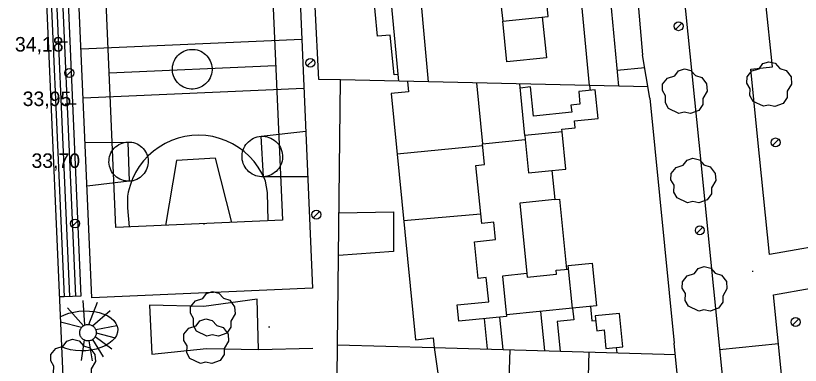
# Model space of a CAD drawing. Extents: x 431390 to 432653, y 4586754 to 4589600.
# Drawn here: x 431800 to 431870.2, y 4586907.1 to 4586938.4 of the extents above; entities that cross this region are included whole.
import ezdxf

# ---------------------------------------------------------------- set-up
doc = ezdxf.new("R2010")
doc.units = 0
for name, color, linetype in [('COM_17LS_LN', 7, 'Continuous'), ('COM_51_LN', 7, 'Continuous'), ('CON_01_LN', 7, 'Continuous'), ('CON_01FI_LN', 7, 'Continuous'), ('CON_03_LN', 7, 'Continuous'), ('CON_04_LN', 7, 'Continuous'), ('CON_15_LN', 7, 'Continuous'), ('CON_16_LN', 7, 'Continuous'), ('CON_18LS_LN', 7, 'Continuous'), ('CON_19_LN', 7, 'Continuous'), ('CON_23_LN', 7, 'Continuous'), ('CON_24LS_LN', 7, 'Continuous'), ('ENE_06_PT', 7, 'Continuous'), ('ORO_03_PT', 7, 'Continuous'), ('ORO_04_PT', 7, 'Continuous'), ('ORO_04_TX', 7, 'Continuous'), ('VEG_03_PT', 7, 'Continuous')]:
    doc.layers.add(name, color=color, linetype=linetype)

msp = doc.modelspace()

# ---------------------------------------------------------------- linework, layer by layer
at = {"layer": 'COM_17LS_LN'}
for points in [[(431853.209, 4587026.07), (431851.172, 4587025.865), (431854.479, 4586993.032), (431857.953, 4586958.536), (431861.124, 4586927.05), (431865.053, 4586888.028), (431868.58, 4586853.01), (431870.706, 4586853.224), (431871.5, 4586845.327)], [(431978.482, 4586940.712), (431979.21, 4586936.465), (431977.301, 4586936.133), (431968.138, 4586934.539), (431952.481, 4586931.815), (431928.554, 4586927.652), (431912.203, 4586924.807), (431895.247, 4586921.857), (431873.934, 4586918.149), (431867.46, 4586917.026), (431866.397, 4586927.581), (431865.787, 4586933.635), (431867.716, 4586933.829), (431867.112, 4586939.828), (431865.183, 4586939.634), (431863.226, 4586959.067), (431861.278, 4586978.415)], [(431874.91, 4586845.69), (431873.853, 4586853.541), (431873.729, 4586854.767), (431875.087, 4586854.904), (431874.927, 4586856.495), (431873.569, 4586856.358), (431870.326, 4586888.559), (431867.823, 4586913.416), (431874.552, 4586914.603), (431895.864, 4586918.311), (431912.821, 4586921.261), (431929.172, 4586924.106), (431935.982, 4586925.291)]]:
    msp.add_lwpolyline(points, dxfattribs=at)
at = {"layer": 'COM_51_LN'}
msp.add_lwpolyline([(431868.266, 4586909.012), (431862.994, 4586908.481)], dxfattribs=at)
at = {"layer": 'CON_01_LN'}
for points in [[(431854.203, 4586956.737), (431856.092, 4586934.904)], [(431856.756, 4586931.032), (431856.092, 4586934.904)], [(431856.756, 4586931.032), (431858.937, 4586909.088)], [(431859.921, 4586899.186), (431858.937, 4586909.088)]]:
    msp.add_lwpolyline(points, dxfattribs=at)
at = {"layer": 'CON_01FI_LN'}
for points in [[(431828.804, 4586908.95), (431829.048, 4586932.666), (431827.13, 4586932.71), (431825.8, 4586958.75)], [(431801.98, 4586957.34), (431806.03, 4586864.43), (431833.508, 4586863.83), (431833.576, 4586865.966), (431837.653, 4586865.916), (431837.679, 4586868.022), (431838.021, 4586873.777), (431833.823, 4586873.778), (431833.91, 4586876.529), (431842.85, 4586876.74), (431852.851, 4586877.287), (431852.6, 4586881.16), (431848.78, 4586880.94), (431848.8, 4586882.78), (431845.66, 4586882.65), (431845.641, 4586885.215), (431839.319, 4586885.285), (431828.566, 4586885.721)], [(431828.804, 4586908.95), (431837.436, 4586908.702), (431838.09, 4586904.139), (431841.489, 4586904.07), (431841.411, 4586899.722), (431828.713, 4586900.09), (431828.566, 4586885.721)]]:
    msp.add_lwpolyline(points, dxfattribs=at)
at = {"layer": 'CON_03_LN'}
for points in [[(431856.585, 4586932.03), (431829.048, 4586932.666)], [(431837.436, 4586908.702), (431859.037, 4586908.081)]]:
    msp.add_lwpolyline(points, dxfattribs=at)
at = {"layer": 'CON_04_LN'}
for points in [[(431853.962, 4586932.091), (431851.55, 4586957.907)], [(431832.476, 4586957.35), (431832.11, 4586955.39), (431834.252, 4586932.546)], [(431848.912, 4586957.642), (431851.315, 4586932.152)], [(431835.115, 4586956.796), (431834.86, 4586955.22), (431836.918, 4586932.484)], [(431834.195, 4586933.154), (431833.853, 4586933.122), (431833.519, 4586936.676), (431832.357, 4586936.567), (431831.729, 4586943.247), (431832.87, 4586943.354), (431832.462, 4586947.694), (431831.302, 4586947.585), (431830.956, 4586951.263), (431832.219, 4586951.382), (431832.06, 4586953.075), (431832.325, 4586953.1)], [(431847.196, 4586942.871), (431840.47, 4586942.18), (431840.78, 4586939.161), (431843.421, 4586939.432), (431843.575, 4586937.932), (431847.66, 4586938.351), (431847.196, 4586942.871)], [(431847.124, 4586938.296), (431847.499, 4586934.639), (431843.95, 4586934.275), (431843.575, 4586937.932)], [(431856.294, 4586933.729), (431853.83, 4586933.502)], [(431835.048, 4586932.527), (431835.14, 4586931.6), (431833.579, 4586931.445), (431835.769, 4586909.397), (431837.351, 4586909.554), (431837.436, 4586908.702)], [(431841.806, 4586926.95), (431841.267, 4586932.384)], [(431845.567, 4586927.674), (431845.105, 4586932.295)], [(431848.889, 4586928.006), (431848.865, 4586928.244), (431850.071, 4586928.365), (431850.007, 4586929.008), (431852.117, 4586929.219), (431851.862, 4586931.762), (431850.378, 4586931.613), (431850.491, 4586930.488), (431849.688, 4586930.408), (431849.752, 4586929.77), (431846.324, 4586929.427), (431846.064, 4586932.026), (431845.141, 4586931.933)], [(431851.433, 4586931.719), (431851.389, 4586932.15)], [(431847.973, 4586924.556), (431849.221, 4586924.681), (431848.889, 4586928.006), (431845.567, 4586927.674), (431845.602, 4586927.327)], [(431843.92, 4586911.47), (431839.641, 4586911.045), (431839.496, 4586912.506), (431842.326, 4586912.787), (431842.111, 4586914.955), (431841.391, 4586914.883), (431841.064, 4586918.17), (431842.926, 4586918.355), (431842.772, 4586919.907), (431841.698, 4586919.8), (431841.182, 4586924.996), (431841.94, 4586925.071), (431841.754, 4586926.945), (431845.602, 4586927.327), (431845.898, 4586924.35), (431847.973, 4586924.556), (431848.233, 4586921.943), (431845.103, 4586921.632), (431845.731, 4586915.312), (431843.56, 4586915.096), (431843.92, 4586911.47)], [(431841.772, 4586926.763), (431834.119, 4586926.005)], [(431848.233, 4586921.943), (431848.673, 4586921.987), (431849.297, 4586915.701)], [(431828.926, 4586920.77), (431833.8, 4586920.86), (431833.8, 4586917.28), (431828.886, 4586916.951)], [(431841.615, 4586920.634), (431834.71, 4586920.055)], [(431849.45, 4586916.042), (431851.597, 4586916.255), (431851.978, 4586912.423), (431849.831, 4586912.21), (431849.45, 4586916.042)], [(431845.731, 4586915.312), (431845.762, 4586914.999), (431848.398, 4586915.264), (431848.363, 4586915.608), (431849.482, 4586915.72)], [(431849.831, 4586912.21), (431843.905, 4586911.619)], [(431849.831, 4586912.21), (431849.929, 4586911.172), (431848.462, 4586911.025), (431848.726, 4586908.377)], [(431851.439, 4586912.37), (431851.565, 4586911.096), (431851.906, 4586911.13)], [(431843.294, 4586911.408), (431843.58, 4586908.525)], [(431846.972, 4586911.925), (431847.322, 4586908.418)], [(431854.026, 4586911.744), (431851.866, 4586911.527), (431851.999, 4586910.2), (431852.647, 4586910.265), (431852.814, 4586908.604), (431854.326, 4586908.756), (431854.026, 4586911.744)], [(431841.93, 4586911.272), (431842.199, 4586908.565)], [(431853.747, 4586908.698), (431853.794, 4586908.232)], [(431844.202, 4586908.507), (431844.073, 4586904.017)], [(431851.281, 4586908.304), (431851.154, 4586903.873)]]:
    msp.add_lwpolyline(points, dxfattribs=at)
at = {"layer": 'CON_15_LN'}
msp.add_lwpolyline([(431821.72, 4586908.53), (431821.61, 4586913.03), (431816.82, 4586912.36), (431811.95, 4586912.49), (431812.18, 4586908.1), (431817.07, 4586908.61), (431821.72, 4586908.53)], dxfattribs=at)
at = {"layer": 'CON_16_LN'}
msp.add_lwpolyline([(431828.713, 4586900.09), (431828.804, 4586908.95)], dxfattribs=at)
at = {"layer": 'CON_18LS_LN'}
for points in [[(431802.213, 4586952.001), (431802.637, 4586952.019), (431804.137, 4586952.084), (431805.827, 4586913.305), (431804.327, 4586913.24), (431803.903, 4586913.221)], [(431802.637, 4586952.019), (431804.327, 4586913.24)], [(431804.827, 4586913.262), (431803.137, 4586952.041)], [(431803.637, 4586952.062), (431805.327, 4586913.283)]]:
    msp.add_lwpolyline(points, dxfattribs=at)
at = {"layer": 'CON_19_LN'}
msp.add_lwpolyline([(431821.72, 4586908.53), (431826.59, 4586908.65)], dxfattribs=at)
at = {"layer": 'CON_23_LN'}
for points in [[(431806.177, 4586910.713), (431806.016, 4586912.893)], [(431806.534, 4586910.763), (431807.298, 4586912.77)], [(431806.048, 4586910.645), (431804.632, 4586912.264)], [(431803.981, 4586911.436), (431804.348, 4586911.617), (431804.755, 4586911.764), (431805.192, 4586911.875), (431805.65, 4586911.946), (431806.117, 4586911.977), (431806.583, 4586911.966), (431807.037, 4586911.913), (431807.468, 4586911.821), (431807.866, 4586911.69), (431808.222, 4586911.524), (431808.529, 4586911.328), (431808.777, 4586911.104), (431808.963, 4586910.86), (431809.08, 4586910.6), (431809.128, 4586910.33), (431809.104, 4586910.057), (431809.009, 4586909.787), (431808.846, 4586909.526), (431808.618, 4586909.281), (431808.33, 4586909.057), (431807.99, 4586908.859), (431807.604, 4586908.693), (431807.183, 4586908.561), (431806.735, 4586908.467), (431806.272, 4586908.413), (431805.804, 4586908.401), (431805.342, 4586908.43), (431804.897, 4586908.5), (431804.479, 4586908.61), (431804.098, 4586908.756)], [(431806.874, 4586910.64), (431808.446, 4586912.004)], [(431805.885, 4586910.499), (431804.002, 4586910.957)], [(431807.11, 4586909.67), (431807.072, 4586909.608), (431807.028, 4586909.549), (431806.979, 4586909.496), (431806.925, 4586909.447), (431806.866, 4586909.404), (431806.803, 4586909.367), (431806.737, 4586909.336), (431806.668, 4586909.312), (431806.597, 4586909.295), (431806.525, 4586909.284), (431806.452, 4586909.281), (431806.379, 4586909.285), (431806.307, 4586909.297), (431806.237, 4586909.315), (431806.168, 4586909.34), (431806.102, 4586909.371), (431806.04, 4586909.409), (431805.982, 4586909.453), (431805.928, 4586909.502), (431805.879, 4586909.557), (431805.836, 4586909.615), (431805.799, 4586909.678), (431805.769, 4586909.744), (431805.744, 4586909.813), (431805.727, 4586909.884), (431805.717, 4586909.956), (431805.714, 4586910.029), (431805.718, 4586910.102), (431805.729, 4586910.174), (431805.747, 4586910.245), (431805.772, 4586910.313), (431805.804, 4586910.379), (431805.842, 4586910.441), (431805.885, 4586910.499), (431805.935, 4586910.553), (431805.989, 4586910.602), (431806.048, 4586910.645), (431806.111, 4586910.682), (431806.177, 4586910.713), (431806.246, 4586910.737), (431806.317, 4586910.754), (431806.389, 4586910.764), (431806.462, 4586910.768), (431806.534, 4586910.763), (431806.606, 4586910.752), (431806.677, 4586910.734), (431806.746, 4586910.709), (431806.811, 4586910.678), (431806.874, 4586910.64), (431806.932, 4586910.596), (431806.986, 4586910.547), (431807.034, 4586910.492), (431807.077, 4586910.433), (431807.114, 4586910.371), (431807.145, 4586910.304), (431807.169, 4586910.236), (431807.187, 4586910.165), (431807.197, 4586910.093), (431807.2, 4586910.02), (431807.196, 4586909.947), (431807.185, 4586909.875), (431807.167, 4586909.804), (431807.142, 4586909.736), (431807.11, 4586909.67)], [(431807.145, 4586910.304), (431809.045, 4586910.677)], [(431807.2, 4586910.02), (431808.877, 4586909.575)], [(431806.102, 4586909.371), (431805.858, 4586907.534)], [(431806.525, 4586909.284), (431806.828, 4586907.509)], [(431806.866, 4586909.404), (431807.818, 4586907.87)], [(431807.11, 4586909.67), (431808.596, 4586908.579)]]:
    msp.add_lwpolyline(points, dxfattribs=at)
at = {"layer": 'CON_24LS_LN'}
for points in [[(431805.108, 4586952.126), (431824.867, 4586952.987), (431826.566, 4586914.02), (431806.807, 4586913.159), (431805.108, 4586952.126)], [(431807.75, 4586947.261), (431822.646, 4586947.91), (431823.859, 4586920.092), (431808.963, 4586919.443), (431807.75, 4586947.261)], [(431825.596, 4586936.273), (431805.837, 4586935.411)], [(431814.013, 4586933.542), (431814.014, 4586933.716), (431814.032, 4586933.89), (431814.067, 4586934.06), (431814.118, 4586934.227), (431814.186, 4586934.387), (431814.269, 4586934.541), (431814.367, 4586934.685), (431814.478, 4586934.819), (431814.602, 4586934.942), (431814.737, 4586935.051), (431814.882, 4586935.147), (431815.037, 4586935.229), (431815.198, 4586935.295), (431815.365, 4586935.344), (431815.536, 4586935.377), (431815.709, 4586935.393), (431815.884, 4586935.393), (431816.057, 4586935.375), (431816.228, 4586935.34), (431816.394, 4586935.288), (431816.555, 4586935.221), (431816.708, 4586935.138), (431816.853, 4586935.04), (431816.987, 4586934.929), (431817.109, 4586934.805), (431817.219, 4586934.67), (431817.315, 4586934.524), (431817.396, 4586934.37), (431817.462, 4586934.209), (431817.512, 4586934.042), (431817.545, 4586933.871), (431817.561, 4586933.697), (431817.56, 4586933.523), (431817.542, 4586933.349), (431817.507, 4586933.179), (431817.456, 4586933.012), (431817.388, 4586932.852), (431817.305, 4586932.698), (431817.207, 4586932.554), (431817.096, 4586932.42), (431816.972, 4586932.297), (431816.837, 4586932.188), (431816.692, 4586932.092), (431816.537, 4586932.01), (431816.376, 4586931.944), (431816.209, 4586931.895), (431816.038, 4586931.862), (431815.865, 4586931.846), (431815.69, 4586931.846), (431815.517, 4586931.864), (431815.346, 4586931.899), (431815.18, 4586931.951), (431815.019, 4586932.018), (431814.866, 4586932.101), (431814.721, 4586932.199), (431814.587, 4586932.31), (431814.465, 4586932.434), (431814.355, 4586932.569), (431814.259, 4586932.715), (431814.178, 4586932.869), (431814.112, 4586933.03), (431814.062, 4586933.197), (431814.029, 4586933.368), (431814.013, 4586933.542)], [(431808.359, 4586933.295), (431823.255, 4586933.945)], [(431806.027, 4586931.049), (431825.786, 4586931.91)], [(431822.582, 4586920.036), (431822.515, 4586922.591), (431822.341, 4586923.59), (431822.289, 4586923.737), (431822.021, 4586924.305), (431821.699, 4586924.844), (431821.325, 4586925.349), (431820.905, 4586925.816), (431820.44, 4586926.239), (431819.937, 4586926.614), (431819.399, 4586926.939), (431818.833, 4586927.209), (431818.242, 4586927.423), (431817.634, 4586927.579), (431817.013, 4586927.674), (431816.386, 4586927.708), (431815.758, 4586927.681), (431815.136, 4586927.592), (431814.526, 4586927.443), (431813.933, 4586927.236), (431813.364, 4586926.971), (431812.823, 4586926.652), (431812.315, 4586926.282), (431811.847, 4586925.864), (431811.421, 4586925.403), (431811.042, 4586924.902), (431810.714, 4586924.366), (431810.44, 4586923.801), (431810.223, 4586923.212), (431810.064, 4586922.604), (431810.007, 4586922.245), (431809.986, 4586921.21), (431810.147, 4586919.495)], [(431821.95, 4586927.61), (431822.128, 4586927.612), (431822.306, 4586927.597), (431822.481, 4586927.564), (431822.652, 4586927.514), (431822.817, 4586927.448), (431822.975, 4586927.366), (431823.124, 4586927.269), (431823.263, 4586927.158), (431823.391, 4586927.033), (431823.505, 4586926.897), (431823.606, 4586926.75), (431823.692, 4586926.594), (431823.762, 4586926.43), (431823.816, 4586926.26), (431823.852, 4586926.086), (431823.872, 4586925.909), (431823.874, 4586925.731), (431823.859, 4586925.553), (431823.826, 4586925.378), (431823.776, 4586925.207), (431823.71, 4586925.042), (431823.628, 4586924.884), (431823.531, 4586924.735), (431823.42, 4586924.596), (431823.295, 4586924.468), (431823.159, 4586924.354), (431823.012, 4586924.253), (431822.856, 4586924.167), (431822.692, 4586924.097), (431822.522, 4586924.043), (431822.348, 4586924.007), (431822.171, 4586923.987), (431821.993, 4586923.985), (431821.815, 4586924), (431821.64, 4586924.033), (431821.469, 4586924.083), (431821.304, 4586924.149), (431821.146, 4586924.231), (431820.997, 4586924.328), (431820.858, 4586924.439), (431820.73, 4586924.564), (431820.616, 4586924.7), (431820.515, 4586924.847), (431820.429, 4586925.003), (431820.359, 4586925.167), (431820.305, 4586925.337), (431820.269, 4586925.511), (431820.249, 4586925.688), (431820.247, 4586925.866), (431820.262, 4586926.044), (431820.295, 4586926.219), (431820.345, 4586926.39), (431820.411, 4586926.555), (431820.493, 4586926.713), (431820.59, 4586926.862), (431820.701, 4586927.001), (431820.826, 4586927.129), (431820.962, 4586927.243), (431821.109, 4586927.344), (431821.265, 4586927.43), (431821.429, 4586927.5), (431821.599, 4586927.554), (431821.773, 4586927.59), (431821.95, 4586927.61)], [(431826.131, 4586923.989), (431822.171, 4586923.987), (431821.95, 4586927.61), (431825.953, 4586928.07)], [(431806.201, 4586927.047), (431810.03, 4586927.1), (431810.15, 4586923.59), (431806.372, 4586923.145)], [(431810.03, 4586927.1), (431810.202, 4586927.097), (431810.374, 4586927.078), (431810.542, 4586927.042), (431810.706, 4586926.989), (431810.864, 4586926.921), (431811.015, 4586926.838), (431811.157, 4586926.74), (431811.289, 4586926.628), (431811.409, 4586926.505), (431811.516, 4586926.37), (431811.609, 4586926.225), (431811.688, 4586926.072), (431811.752, 4586925.912), (431811.8, 4586925.746), (431811.831, 4586925.577), (431811.845, 4586925.405), (431811.842, 4586925.233), (431811.823, 4586925.061), (431811.787, 4586924.893), (431811.734, 4586924.729), (431811.666, 4586924.571), (431811.583, 4586924.42), (431811.485, 4586924.278), (431811.373, 4586924.146), (431811.25, 4586924.026), (431811.115, 4586923.919), (431810.97, 4586923.826), (431810.817, 4586923.747), (431810.657, 4586923.683), (431810.491, 4586923.635), (431810.322, 4586923.604), (431810.15, 4586923.59), (431809.978, 4586923.593), (431809.806, 4586923.612), (431809.638, 4586923.648), (431809.474, 4586923.701), (431809.316, 4586923.769), (431809.165, 4586923.852), (431809.023, 4586923.95), (431808.891, 4586924.062), (431808.771, 4586924.185), (431808.664, 4586924.32), (431808.571, 4586924.465), (431808.492, 4586924.618), (431808.428, 4586924.778), (431808.38, 4586924.944), (431808.349, 4586925.113), (431808.335, 4586925.285), (431808.338, 4586925.457), (431808.357, 4586925.629), (431808.393, 4586925.797), (431808.446, 4586925.961), (431808.514, 4586926.119), (431808.597, 4586926.27), (431808.695, 4586926.412), (431808.807, 4586926.544), (431808.93, 4586926.664), (431809.065, 4586926.771), (431809.21, 4586926.864), (431809.363, 4586926.943), (431809.523, 4586927.007), (431809.689, 4586927.055), (431809.858, 4586927.086), (431810.03, 4586927.1)], [(431819.337, 4586919.895), (431817.88, 4586925.64), (431814.38, 4586925.45), (431813.386, 4586919.636)]]:
    msp.add_lwpolyline(points, dxfattribs=at)
at = {"layer": 'ENE_06_PT'}
for p, q in [((431859.602, 4586937.752), (431859.036, 4586937.186)), ((431826.642, 4586934.472), (431826.076, 4586933.906)), ((431805.062, 4586933.562), (431804.496, 4586932.996)), ((431868.282, 4586927.342), (431867.716, 4586926.776)), ((431827.182, 4586920.882), (431826.616, 4586920.316)), ((431805.582, 4586920.082), (431805.016, 4586919.516)), ((431861.502, 4586919.472), (431860.936, 4586918.906)), ((431870.072, 4586911.262), (431869.506, 4586910.696))]:
    msp.add_line(p, q, dxfattribs=at)
for centre in [(431859.319, 4586937.469), (431826.359, 4586934.189), (431804.779, 4586933.279), (431867.999, 4586927.059), (431826.899, 4586920.599), (431805.299, 4586919.799), (431861.219, 4586919.189), (431869.789, 4586910.979)]:
    msp.add_circle(centre, 0.4, dxfattribs=at)
at = {"layer": 'ORO_03_PT'}
for p, q in [((431816.783, 4586919.786), (431816.883, 4586919.786)), ((431865.902, 4586915.53), (431866.002, 4586915.53)), ((431822.62, 4586910.55), (431822.72, 4586910.55))]:
    msp.add_line(p, q, dxfattribs=at)
at = {"layer": 'ORO_04_PT'}
for p, q in [((431803.61, 4586936.07), (431804.61, 4586936.07)), ((431804.4, 4586930.53), (431805.4, 4586930.53))]:
    msp.add_line(p, q, dxfattribs=at)
at = {"layer": 'VEG_03_PT'}
for points in [[(431866.91, 4586930.3), (431865.983, 4586930.735), (431865.695, 4586931.256), (431865.718, 4586931.87), (431865.436, 4586932.362), (431865.444, 4586932.925), (431865.885, 4586933.46), (431866.538, 4586933.664), (431866.873, 4586934.115), (431867.399, 4586934.285), (431867.979, 4586934.152), (431868.379, 4586933.686), (431868.953, 4586933.516), (431869.387, 4586932.933), (431869.436, 4586932.291), (431869.053, 4586931.644), (431869.053, 4586931.094), (431868.681, 4586930.56), (431867.942, 4586930.285), (431867.377, 4586930.413), (431866.91, 4586930.3)], [(431859.354, 4586929.661), (431858.427, 4586930.096), (431858.139, 4586930.617), (431858.162, 4586931.231), (431857.88, 4586931.723), (431857.888, 4586932.286), (431858.329, 4586932.821), (431858.982, 4586933.025), (431859.317, 4586933.476), (431859.843, 4586933.646), (431860.423, 4586933.513), (431860.823, 4586933.047), (431861.397, 4586932.877), (431861.831, 4586932.294), (431861.88, 4586931.652), (431861.497, 4586931.005), (431861.497, 4586930.455), (431861.125, 4586929.921), (431860.386, 4586929.646), (431859.821, 4586929.774), (431859.354, 4586929.661)], [(431860.114, 4586921.661), (431859.187, 4586922.096), (431858.899, 4586922.617), (431858.922, 4586923.231), (431858.64, 4586923.723), (431858.648, 4586924.286), (431859.089, 4586924.821), (431859.742, 4586925.025), (431860.077, 4586925.476), (431860.603, 4586925.646), (431861.183, 4586925.513), (431861.583, 4586925.047), (431862.157, 4586924.877), (431862.591, 4586924.294), (431862.64, 4586923.652), (431862.257, 4586923.005), (431862.257, 4586922.455), (431861.885, 4586921.921), (431861.146, 4586921.646), (431860.581, 4586921.774), (431860.114, 4586921.661)], [(431861.124, 4586911.961), (431860.197, 4586912.396), (431859.909, 4586912.917), (431859.932, 4586913.531), (431859.65, 4586914.023), (431859.658, 4586914.586), (431860.099, 4586915.121), (431860.752, 4586915.325), (431861.087, 4586915.776), (431861.613, 4586915.946), (431862.193, 4586915.813), (431862.593, 4586915.347), (431863.167, 4586915.177), (431863.601, 4586914.594), (431863.65, 4586913.952), (431863.267, 4586913.305), (431863.267, 4586912.755), (431862.895, 4586912.221), (431862.156, 4586911.946), (431861.591, 4586912.074), (431861.124, 4586911.961)], [(431817.104, 4586909.721), (431816.177, 4586910.156), (431815.889, 4586910.677), (431815.912, 4586911.291), (431815.63, 4586911.783), (431815.638, 4586912.346), (431816.079, 4586912.881), (431816.732, 4586913.085), (431817.067, 4586913.536), (431817.593, 4586913.706), (431818.173, 4586913.573), (431818.573, 4586913.107), (431819.147, 4586912.937), (431819.581, 4586912.354), (431819.63, 4586911.712), (431819.247, 4586911.065), (431819.247, 4586910.515), (431818.875, 4586909.981), (431818.136, 4586909.706), (431817.571, 4586909.834), (431817.104, 4586909.721)], [(431816.514, 4586907.271), (431815.587, 4586907.706), (431815.299, 4586908.227), (431815.322, 4586908.841), (431815.04, 4586909.333), (431815.048, 4586909.896), (431815.489, 4586910.431), (431816.142, 4586910.635), (431816.477, 4586911.086), (431817.003, 4586911.256), (431817.583, 4586911.123), (431817.983, 4586910.657), (431818.557, 4586910.487), (431818.991, 4586909.904), (431819.04, 4586909.262), (431818.657, 4586908.615), (431818.657, 4586908.065), (431818.285, 4586907.531), (431817.546, 4586907.256), (431816.981, 4586907.384), (431816.514, 4586907.271)], [(431804.594, 4586905.451), (431803.667, 4586905.886), (431803.379, 4586906.407), (431803.402, 4586907.021), (431803.12, 4586907.513), (431803.128, 4586908.076), (431803.569, 4586908.611), (431804.222, 4586908.815), (431804.557, 4586909.266), (431805.083, 4586909.436), (431805.663, 4586909.303), (431806.063, 4586908.837), (431806.637, 4586908.667), (431807.071, 4586908.084), (431807.12, 4586907.442), (431806.737, 4586906.795), (431806.737, 4586906.245), (431806.365, 4586905.711), (431805.626, 4586905.436), (431805.061, 4586905.564), (431804.594, 4586905.451)]]:
    msp.add_lwpolyline(points, dxfattribs=at)

# ---------------------------------------------------------------- texts
at = {"layer": 'ORO_04_TX'}
for s, p in [('34,18', (431799.92, 4586935.2)), ('33,95', (431800.61, 4586930.32)), ('33,70', (431801.4, 4586924.78))]:
    msp.add_text(s, height=1.3, dxfattribs=at).set_placement(p)

doc.saveas('drawing.dxf')
